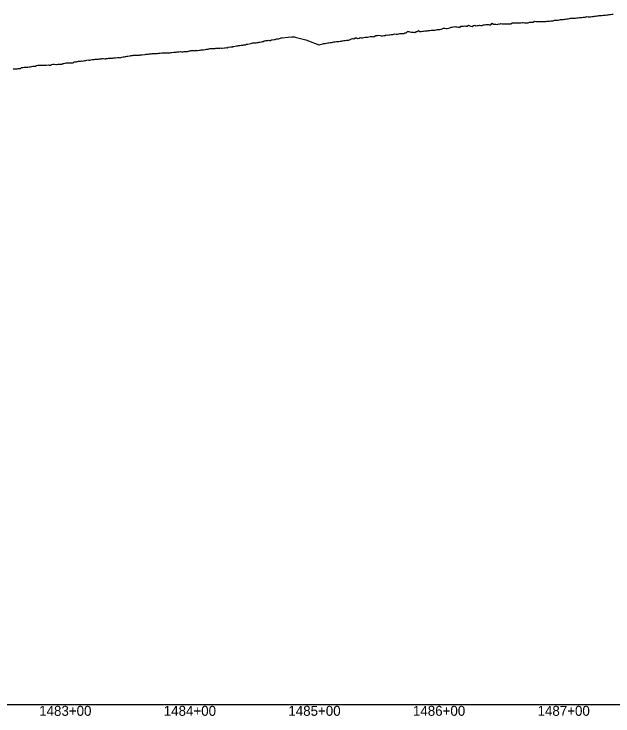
# Model space of a CAD drawing. Extents: x -3793 to 50787, y -1075 to 6138.
# Drawn here: x 35638 to 36119, y 991 to 1554 of the extents above; entities that cross this region are included whole.
import ezdxf

# ---------------------------------------------------------------- set-up
doc = ezdxf.new("R2010")
doc.units = 0
for name, color, linetype in [('RD_DDB_Profile_EX', 7, 'Continuous'), ('RD_DDB_StaTX', 7, 'Continuous'), ('RD_GPK_Profile_Cell', 7, 'Continuous')]:
    doc.layers.add(name, color=color, linetype=linetype)

msp = doc.modelspace()

# ---------------------------------------------------------------- linework, layer by layer
at = {"layer": 'RD_DDB_Profile_EX'}
for points in [[(36089.952311, 1550.842495), (36090.95554, 1550.89827), (36091.958422, 1551.152395), (36092.952077, 1551.153955), (36093.955357, 1551.17312), (36094.958206, 1551.227575), (36095.961497, 1551.27975), (36096.955194, 1551.43605), (36097.958472, 1551.96373), (36098.961277, 1551.63973), (36099.964567, 1551.64913), (36100.958308, 1551.69798), (36101.961054, 1551.80985), (36102.964344, 1551.91437), (36103.958088, 1552.10442), (36104.458441, 1552.1564), (36104.960866, 1552.22551), (36105.964201, 1552.374415), (36106.967536, 1552.52018), (36107.961425, 1552.562555), (36108.964164, 1552.61657), (36109.967496, 1552.817535), (36110.970396, 1552.91946), (36111.96366, 1552.979225), (36112.96699, 1552.94596), (36113.970351, 1553.09427), (36114.973022, 1553.295185), (36115.96694, 1553.355525), (36116.9703, 1553.54667), (36117.98255, 1553.66293), (36118.966956, 1553.858055)], [(35994.958022, 1543.339345), (35995.962156, 1543.195215), (35996.265567, 1543.454945), (35996.95459, 1544.03028), (35997.956548, 1544.029585), (35998.958656, 1544.07793), (35999.960799, 1544.323735), (36000.953022, 1544.227575), (36001.955162, 1544.086945), (36002.957268, 1544.87611), (36003.94968, 1544.2844), (36004.953594, 1544.03971), (36005.955699, 1543.9903), (36006.957836, 1544.67861), (36007.950058, 1544.8748), (36008.952193, 1544.485775), (36009.954284, 1544.535395), (36010.956199, 1544.729025), (36011.948489, 1544.87531), (36012.950545, 1544.776335), (36013.952598, 1544.628485), (36014.946698, 1545.27418), (36015.948753, 1545.323915), (36016.950779, 1545.568975), (36017.952707, 1545.56817), (36018.944974, 1545.568115), (36019.947023, 1545.2713), (36020.948939, 1545.174055), (36021.950989, 1546.50726), (36022.943254, 1545.664895), (36023.313786, 1545.66555), (36023.947203, 1545.6726), (36024.94907, 1545.621745), (36025.94124, 1545.57057), (36026.943187, 1545.91457), (36027.945051, 1545.864735), (36028.947005, 1546.361595), (36029.939149, 1546.013625), (36030.941096, 1546.063615), (36031.942986, 1546.01333), (36032.946893, 1546.065745), (36033.93903, 1546.11446), (36034.94098, 1546.112325), (36035.942881, 1546.110815), (36036.94483, 1546.060125), (36037.936868, 1546.70623), (36038.938744, 1546.903875), (36039.940601, 1546.803165), (36040.932617, 1546.75231), (36041.934492, 1546.850875), (36042.606491, 1546.782925), (36042.936741, 1546.750735), (36043.939747, 1546.753015), (36044.932703, 1546.90491), (36045.935693, 1547.00742), (36046.938698, 1547.059905), (36047.941704, 1546.815015), (36048.934643, 1546.86721), (36049.937649, 1546.869815), (36050.362004, 1546.871015), (36050.940695, 1546.87313), (36051.933777, 1547.224195), (36052.936789, 1547.276835), (36053.939869, 1547.329395), (36054.94295, 1547.33421), (36055.935958, 1548.178235), (36056.939038, 1547.9839), (36057.942118, 1547.98713), (36058.945198, 1547.89297), (36059.938204, 1547.951365), (36060.941283, 1547.95393), (36061.944363, 1547.904905), (36062.947283, 1547.907205), (36063.940451, 1547.91223), (36064.943605, 1547.96666), (36065.946759, 1548.124885), (36066.939336, 1548.07246), (36067.942482, 1548.075295), (36068.945636, 1548.375225), (36069.948584, 1548.38296), (36070.941877, 1548.386295), (36071.945031, 1548.87789), (36072.948173, 1548.84497), (36073.951085, 1548.896425), (36074.944413, 1548.997225), (36075.947567, 1549.102205), (36076.950438, 1549.354415), (36077.410223, 1549.379045), (36077.943833, 1549.41197), (36078.947062, 1549.46189), (36079.95029, 1549.75704), (36080.953194, 1549.813665), (36081.946663, 1550.07972), (36082.949891, 1550.083985), (36083.95278, 1550.35958), (36084.95598, 1550.41798), (36085.949489, 1550.437125), (36086.952717, 1550.491125), (36087.955565, 1550.55076), (36088.958782, 1550.65298), (36089.952311, 1550.842495)], [(35896.97801, 1531.774765), (35897.980708, 1531.87564), (35898.973619, 1531.92944), (35899.976213, 1532.080945), (35900.978889, 1532.13187), (35901.596803, 1532.257165), (35901.971782, 1532.328425), (35902.974408, 1532.582575), (35903.97689, 1532.63198), (35904.979513, 1532.83139), (35905.97237, 1532.93483), (35906.974995, 1532.98614), (35907.977465, 1533.382165), (35908.97033, 1533.93034), (35909.972954, 1534.13088), (35910.975579, 1534.035615), (35911.978036, 1534.722695), (35912.97091, 1534.86745), (35913.973534, 1534.29434), (35915.120912, 1534.39397), (35915.978539, 1534.98409), (35916.971349, 1534.74006), (35917.973899, 1534.6912), (35918.976263, 1534.994635), (35919.969078, 1535.239795), (35920.971627, 1535.29014), (35921.976079, 1535.294655), (35922.978415, 1535.446725), (35923.971252, 1535.94101), (35924.9738, 1535.94591), (35925.976349, 1535.75181), (35926.968971, 1535.65525), (35927.97152, 1536.44528), (35928.645021, 1536.546275), (35928.974045, 1536.594585), (35929.976483, 1536.594605), (35930.969069, 1536.841145), (35931.971544, 1536.601775), (35932.97402, 1536.510525), (35933.976458, 1536.46247), (35934.969043, 1536.61007), (35935.971519, 1536.70922), (35936.973994, 1537.154475), (35937.966735, 1536.96069), (35938.969017, 1537.307875), (35939.971492, 1537.262905), (35940.973968, 1537.362045), (35942.169131, 1537.490755), (35942.968933, 1537.60736), (35943.971336, 1537.909155), (35944.964007, 1537.71613), (35945.96641, 1537.763965), (35946.968619, 1538.070645), (35947.971022, 1538.254775), (35948.963692, 1538.30484), (35949.966095, 1538.311505), (35950.968305, 1538.27398), (35951.970709, 1538.66793), (35952.963415, 1538.672015), (35953.965626, 1539.797545), (35954.968066, 1539.94457), (35955.960753, 1539.55531), (35956.96312, 1539.206875), (35957.967136, 1539.26229), (35958.969508, 1539.267075), (35959.962194, 1539.126335), (35960.964321, 1539.7604), (35961.966692, 1539.761045), (35962.969023, 1540.647445), (35963.961505, 1539.965595), (35964.963836, 1539.967075), (35965.966205, 1540.113665), (35966.960745, 1540.211285), (35967.962905, 1540.2588), (35969.217349, 1540.44198), (35969.967553, 1540.512015), (35970.959964, 1540.609615), (35971.962222, 1540.755775), (35972.964519, 1540.85312), (35973.966577, 1540.911525), (35974.959186, 1540.965205), (35975.961443, 1540.960395), (35976.965639, 1541.154155), (35977.95805, 1541.365515), (35978.960307, 1541.3647), (35979.962603, 1541.55987), (35980.964657, 1541.84892), (35981.957268, 1541.896635), (35982.959507, 1542.59098), (35983.961728, 1542.49227), (35984.963719, 1542.300175), (35985.958159, 1542.25606), (35986.960381, 1542.450065), (35987.962363, 1542.89817), (35988.964586, 1543.288495), (35989.957077, 1543.27827), (35990.959105, 1543.475875), (35991.961288, 1543.8735), (35992.953806, 1543.67695), (35993.955985, 1543.67733), (35994.958022, 1543.339345)], [(35789.682388, 1525.091985), (35790.35387, 1525.09253), (35792.029735, 1525.44659), (35792.679716, 1525.641615), (35793.403929, 1525.59981), (35793.99567, 1525.805125), (35794.652955, 1525.97003), (35795.303129, 1526.16745), (35797.055997, 1526.24896), (35797.696295, 1526.3439), (35798.337582, 1526.280545), (35798.979294, 1526.279505), (35799.620053, 1526.248165), (35800.256963, 1526.503205), (35802.090777, 1526.566585), (35802.714629, 1526.411685), (35803.337913, 1526.379495), (35803.961224, 1526.660135), (35804.579855, 1526.53467), (35805.202693, 1526.535265), (35807.131252, 1526.70593), (35807.734188, 1526.76513), (35808.338058, 1527.006845), (35808.936268, 1526.794955), (35809.539416, 1526.795745), (35810.141662, 1527.15772), (35812.177417, 1527.457425), (35812.757359, 1527.427405), (35813.33826, 1527.37032), (35813.911319, 1527.864305), (35814.487216, 1527.808285), (35816.681976, 1528.28811), (35817.236705, 1528.31885), (35817.788446, 1528.404215), (35818.337051, 1528.490995), (35818.88188, 1528.602485), (35819.423804, 1528.68625), (35820.452148, 1528.83145), (35821.798567, 1529.021815), (35822.310594, 1529.22964), (35822.824917, 1529.25772), (35823.336071, 1529.287215), (35823.843416, 1529.28958), (35824.347815, 1529.26668), (35824.849295, 1529.59642), (35825.347878, 1529.62298), (35825.838647, 1529.62526), (35828.383147, 1530.18074), (35829.111807, 1530.405295), (35829.845605, 1530.66603), (35830.577185, 1530.742875), (35831.934661, 1530.895815), (35832.660534, 1530.863765), (35833.384036, 1530.90661), (35834.10465, 1531.05452), (35834.82296, 1531.309795), (35835.538959, 1531.38501), (35836.97562, 1531.6925), (35837.678724, 1531.80559), (35838.385253, 1531.950775), (35839.089443, 1532.306335), (35839.791306, 1532.380045), (35840.490854, 1532.55859), (35842.011486, 1532.727195), (35842.704411, 1532.93962), (35843.393579, 1532.73695), (35844.080407, 1532.70635), (35844.758152, 1533.05211), (35845.440393, 1533.157725), (35847.049447, 1533.433805), (35847.724169, 1533.507175), (35848.39511, 1533.678165), (35849.063624, 1533.848535), (35849.729722, 1533.88509), (35850.393419, 1534.08771), (35852.097073, 1534.39621), (35852.745654, 1534.694785), (35853.397012, 1534.892715), (35857.86763, 1535.27239), (35858.329929, 1535.377655), (35861.024475, 1535.47078), (35863.438764, 1535.527825), (35863.877565, 1535.41408), (35872.429622, 1533.228915), (35874.548585, 1532.416445), (35882.84556, 1529.23568), (35883.20976, 1529.11723), (35883.972337, 1529.31557), (35884.975114, 1529.71538), (35885.977879, 1530.06539), (35886.980655, 1530.21637), (35888.072694, 1530.341825), (35888.976247, 1530.566915), (35889.978933, 1530.717035), (35890.971816, 1530.820785), (35891.974441, 1530.924505), (35892.977124, 1531.074705), (35893.979823, 1531.22059), (35894.97272, 1531.469885), (35895.97533, 1531.522055), (35896.97801, 1531.774765)], [(35708.3082, 1517.97896), (35709.072731, 1518.100375), (35709.832902, 1518.066355), (35711.056015, 1518.0122), (35711.813653, 1517.980255), (35712.259274, 1518.07092), (35712.563076, 1518.132765), (35713.307112, 1518.211635), (35714.045394, 1518.36217), (35714.775915, 1518.365825), (35716.143955, 1518.56138), (35716.86245, 1518.5654), (35717.584114, 1518.571525), (35718.298774, 1518.64677), (35719.00689, 1518.758645), (35719.710577, 1518.83261), (35721.226683, 1518.91512), (35721.923964, 1519.023595), (35722.613034, 1518.924345), (35723.296774, 1518.861775), (35723.974889, 1519.035065), (35724.645455, 1519.24213), (35725.783383, 1519.429605), (35726.325552, 1519.519005), (35726.988982, 1519.525655), (35727.637658, 1519.757485), (35728.287638, 1519.82738), (35728.931959, 1519.95945), (35729.568764, 1520.059605), (35731.425305, 1520.346535), (35732.050198, 1520.47413), (35732.670951, 1520.57154), (35733.284946, 1520.6359), (35733.892655, 1520.82261), (35734.496054, 1520.7643), (35736.535256, 1520.893525), (35737.12406, 1520.926995), (35737.705086, 1520.958725), (35738.275332, 1520.934125), (35738.84603, 1520.99404), (35739.409615, 1521.139675), (35739.969988, 1521.08529), (35740.521197, 1521.088645), (35741.071492, 1521.146825), (35743.348575, 1521.534665), (35744.112593, 1521.61905), (35744.873598, 1521.700525), (35746.087243, 1521.761045), (35746.846958, 1521.844235), (35747.601286, 1521.887015), (35748.352064, 1521.931965), (35749.093649, 1522.119095), (35749.844251, 1522.15467), (35751.126778, 1522.216385), (35751.868581, 1522.25373), (35752.831602, 1522.237215), (35753.34434, 1522.28914), (35754.087228, 1522.398575), (35754.829548, 1522.473125), (35755.574127, 1522.36026), (35756.882762, 1522.624535), (35757.617292, 1522.625145), (35758.344402, 1522.69601), (35759.079116, 1522.696605), (35759.815335, 1522.62096), (35761.17316, 1522.682465), (35761.899521, 1522.71933), (35762.618247, 1522.82843), (35763.344215, 1522.86239), (35764.070422, 1523.00796), (35764.798164, 1523.078375), (35766.355711, 1523.209915), (35766.910372, 1523.21039), (35767.626716, 1523.279815), (35768.344054, 1523.352165), (35769.062017, 1523.42175), (35769.772239, 1523.422305), (35770.49187, 1523.63536), (35771.929222, 1523.6966), (35772.636809, 1523.66201), (35773.344168, 1523.62474), (35774.051694, 1523.625465), (35774.753754, 1523.906065), (35775.461274, 1523.8007), (35776.95116, 1523.84969), (35777.647066, 1523.813005), (35778.344035, 1524.091885), (35779.033634, 1524.30093), (35779.87982, 1524.37134), (35780.428078, 1524.50877), (35781.975317, 1524.50247), (35782.659138, 1524.501315), (35783.337117, 1524.43344), (35784.02252, 1524.774165), (35784.707113, 1524.70625), (35785.394048, 1524.671065), (35787.000501, 1524.8586), (35787.672492, 1524.92626), (35788.337392, 1525.09256), (35789.009159, 1525.12663), (35789.682388, 1525.091985)], [(35637.497703, 1509.78328), (35638.500004, 1509.83597), (35639.504525, 1509.891455), (35640.625298, 1509.950845), (35641.665126, 1510.056475), (35642.572516, 1510.059705), (35643.348068, 1510.150795), (35644.25345, 1510.86718), (35644.638728, 1510.958925), (35645.300277, 1511.099035), (35646.29869, 1511.24731), (35647.326139, 1511.350155), (35648.033515, 1511.21103), (35648.338899, 1511.15287), (35649.335268, 1511.167645), (35650.358549, 1511.627615), (35651.359331, 1511.64258), (35652.353365, 1511.70679), (35653.331377, 1511.962025), (35654.313419, 1512.02482), (35655.395531, 1512.09061), (35656.38149, 1512.59293), (35657.359921, 1512.747055), (35658.333592, 1512.856315), (35659.302211, 1512.81567), (35660.444896, 1512.89184), (35661.415241, 1512.90522), (35662.377868, 1512.913765), (35663.335562, 1512.926985), (35664.288117, 1512.93543), (35665.496767, 1513.056115), (35666.448417, 1512.82871), (35667.386841, 1512.74858), (35668.328366, 1513.36799), (35669.263755, 1513.56721), (35670.192323, 1513.57863), (35670.541145, 1513.640805), (35671.686947, 1513.3755), (35672.405975, 1513.387615), (35673.329927, 1513.58193), (35674.247574, 1513.64258), (35675.161157, 1513.65201), (35675.595009, 1513.69722), (35676.514108, 1513.531805), (35677.42521, 1514.17679), (35678.331175, 1514.19101), (35679.230055, 1514.384865), (35680.116054, 1514.75185), (35680.645682, 1514.79346), (35681.545271, 1514.762205), (35682.436833, 1514.6822), (35683.323258, 1514.695735), (35684.204294, 1514.66045), (35685.211056, 1514.6864), (35685.708363, 1514.732905), (35686.585412, 1515.56868), (35687.458371, 1515.450595), (35688.323993, 1515.46278), (35689.184076, 1515.6856), (35690.036509, 1515.996285), (35690.77501, 1516.058955), (35691.629953, 1516.108705), (35692.480808, 1516.204045), (35693.324805, 1516.168925), (35694.154034, 1516.30499), (35694.987405, 1516.47862), (35695.832857, 1516.54981), (35696.667982, 1516.7665), (35697.494901, 1517.1015), (35698.316544, 1516.86431), (35698.735165, 1516.86741), (35699.132603, 1516.870445), (35699.940889, 1517.163915), (35700.906657, 1517.27209), (35701.717199, 1517.361955), (35702.519415, 1517.44793), (35703.316229, 1517.536285), (35704.107373, 1517.6606), (35704.883071, 1517.66844), (35705.976896, 1517.69114), (35706.759106, 1517.96759), (35707.537137, 1517.935915), (35708.3082, 1517.97896)]]:
    msp.add_lwpolyline(points, dxfattribs=at)
at = {"layer": 'RD_GPK_Profile_Cell'}
msp.add_line((1000, 1000), (46600, 1000), dxfattribs=at)

# ---------------------------------------------------------------- texts
at = {"layer": 'RD_DDB_StaTX'}
for s, p in [('1483+00', (35658.415471, 991)), ('1484+00', (35758.415471, 991)), ('1485+00', (35858.415471, 991)), ('1486+00', (35958.415471, 991)), ('1487+00', (36058.415471, 991))]:
    msp.add_text(s, height=8, dxfattribs=at).set_placement(p)

doc.saveas('drawing.dxf')
